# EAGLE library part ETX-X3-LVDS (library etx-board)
VGA, LCD, Video, COM1, COM2, LPT/Floppy, IrDA, Mouse, Keyboard LVDS INTERFACE PINOUT, PARALLEL PORT MODE PINOUT ETX Board Connector 100 Pos. Source: www.kontron.com/techlib/whitepapers/etx_spec.pdf
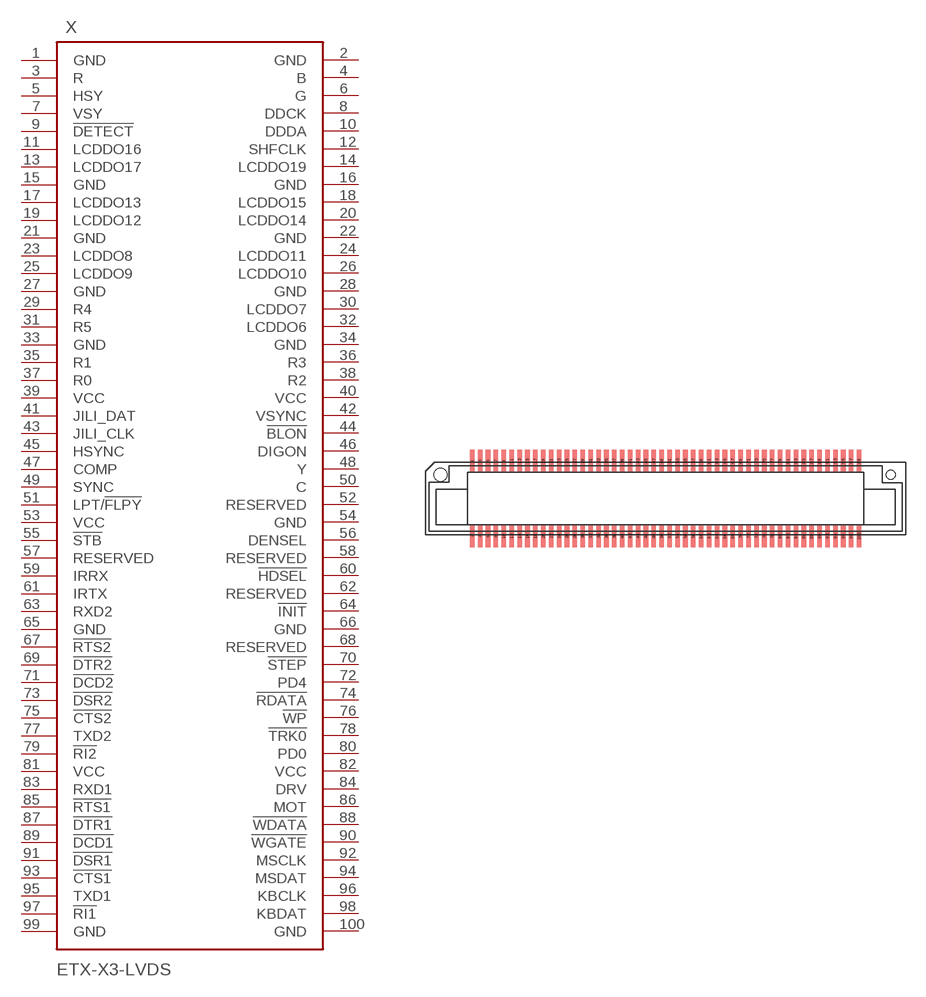
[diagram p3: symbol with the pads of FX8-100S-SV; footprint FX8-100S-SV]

Designator prefix X

## ETX-X3-LVDS  [FX8-100S-SV]
1  GND  pwr
2  GND  pwr
3  R
4  B
5  HSY
6  G
7  VSY
8  DDCK
9  !DETECT
10  DDDA
11  LCDDO16
12  SHFCLK
13  LCDDO17
14  LCDDO19
15  GND  pwr
16  GND  pwr
17  LCDDO13
18  LCDDO15
19  LCDDO12
20  LCDDO14
21  GND  pwr
22  GND  pwr
23  LCDDO8
24  LCDDO11
25  LCDDO9
26  LCDDO10
27  GND  pwr
28  GND  pwr
29  R4
30  LCDDO7
31  R5
32  LCDDO6
33  GND  pwr
34  GND  pwr
35  R1
36  R3
37  R0
38  R2
39  VCC  pwr
40  VCC  pwr
41  JILI_DAT
42  VSYNC
43  JILI_CLK
44  !BLON
45  HSYNC
46  DIGON
47  COMP
48  Y
49  SYNC
50  C
51  LPT/!FLPY
52  RESERVED
53  VCC  pwr
54  GND  pwr
55  !STB
56  DENSEL
57  RESERVED
58  RESERVED
59  IRRX
60  !HDSEL
61  IRTX
62  RESERVED
63  RXD2
64  !INIT
65  GND  pwr
66  GND  pwr
67  !RTS2
68  RESERVED
69  !DTR2
70  !STEP
71  !DCD2
72  PD4
73  !DSR2
74  !RDATA
75  !CTS2
76  !WP
77  TXD2
78  !TRK0
79  !RI2
80  PD0
81  VCC  pwr
82  VCC  pwr
83  RXD1
84  DRV
85  !RTS1
86  MOT
87  !DTR1
88  !WDATA
89  !DCD1
90  !WGATE
91  !DSR1
92  MSCLK
93  !CTS1
94  MSDAT
95  TXD1
96  KBCLK
97  !RI1
98  KBDAT
99  GND  pwr
100  GND  pwr

## Footprint FX8-100S-SV (pad centres in mm)
HIROSE - ETX Board Connector 100 Pos. Source: www.hirose.co.jp/cataloge_hp/e57800016.pdf www.kontron.com/techlib/whitepapers/etx_spec.pdf
smd 0.35 x 1.7: 1 -14.7,2.85; 2 -14.7,-2.85; 3 -14.1,2.85; 4 -14.1,-2.85; 5 -13.5,2.85; 6 -13.5,-2.85; 7 -12.9,2.85; 8 -12.9,-2.85; 9 -12.3,2.85; 10 -12.3,-2.85; 11 -11.7,2.85; 12 -11.7,-2.85; 13 -11.1,2.85; 14 -11.1,-2.85; 15 -10.5,2.85; 16 -10.5,-2.85; 17 -9.9,2.85; 18 -9.9,-2.85; 19 -9.3,2.85; 20 -9.3,-2.85; 21 -8.7,2.85; 22 -8.7,-2.85; 23 -8.1,2.85; 24 -8.1,-2.85; 25 -7.5,2.85; 26 -7.5,-2.85; 27 -6.9,2.85; 28 -6.9,-2.85; 29 -6.3,2.85; 30 -6.3,-2.85; 31 -5.7,2.85; 32 -5.7,-2.85; 33 -5.1,2.85; 34 -5.1,-2.85; 35 -4.5,2.85; 36 -4.5,-2.85; 37 -3.9,2.85; 38 -3.9,-2.85; 39 -3.3,2.85; 40 -3.3,-2.85; 41 -2.7,2.85; 42 -2.7,-2.85; 43 -2.1,2.85; 44 -2.1,-2.85; 45 -1.5,2.85; 46 -1.5,-2.85; 47 -0.9,2.85; 48 -0.9,-2.85; 49 -0.3,2.85; 50 -0.3,-2.85; 51 0.3,2.85; 52 0.3,-2.85; 53 0.9,2.85; 54 0.9,-2.85; 55 1.5,2.85; 56 1.5,-2.85; 57 2.1,2.85; 58 2.1,-2.85; 59 2.7,2.85; 60 2.7,-2.85; 61 3.3,2.85; 62 3.3,-2.85; 63 3.9,2.85; 64 3.9,-2.85; 65 4.5,2.85; 66 4.5,-2.85; 67 5.1,2.85; 68 5.1,-2.85; 69 5.7,2.85; 70 5.7,-2.85; 71 6.3,2.85; 72 6.3,-2.85; 73 6.9,2.85; 74 6.9,-2.85; 75 7.5,2.85; 76 7.5,-2.85; 77 8.1,2.85; 78 8.1,-2.85; 79 8.7,2.85; 80 8.7,-2.85; 81 9.3,2.85; 82 9.3,-2.85; 83 9.9,2.85; 84 9.9,-2.85; 85 10.5,2.85; 86 10.5,-2.85; 87 11.1,2.85; 88 11.1,-2.85; 89 11.7,2.85; 90 11.7,-2.85; 91 12.3,2.85; 92 12.3,-2.85; 93 12.9,2.85; 94 12.9,-2.85; 95 13.5,2.85; 96 13.5,-2.85; 97 14.1,2.85; 98 14.1,-2.85; 99 14.7,2.85; 100 14.7,-2.85
hole 1 at -17.1,1.8
hole 0.7 at 17.1,1.8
